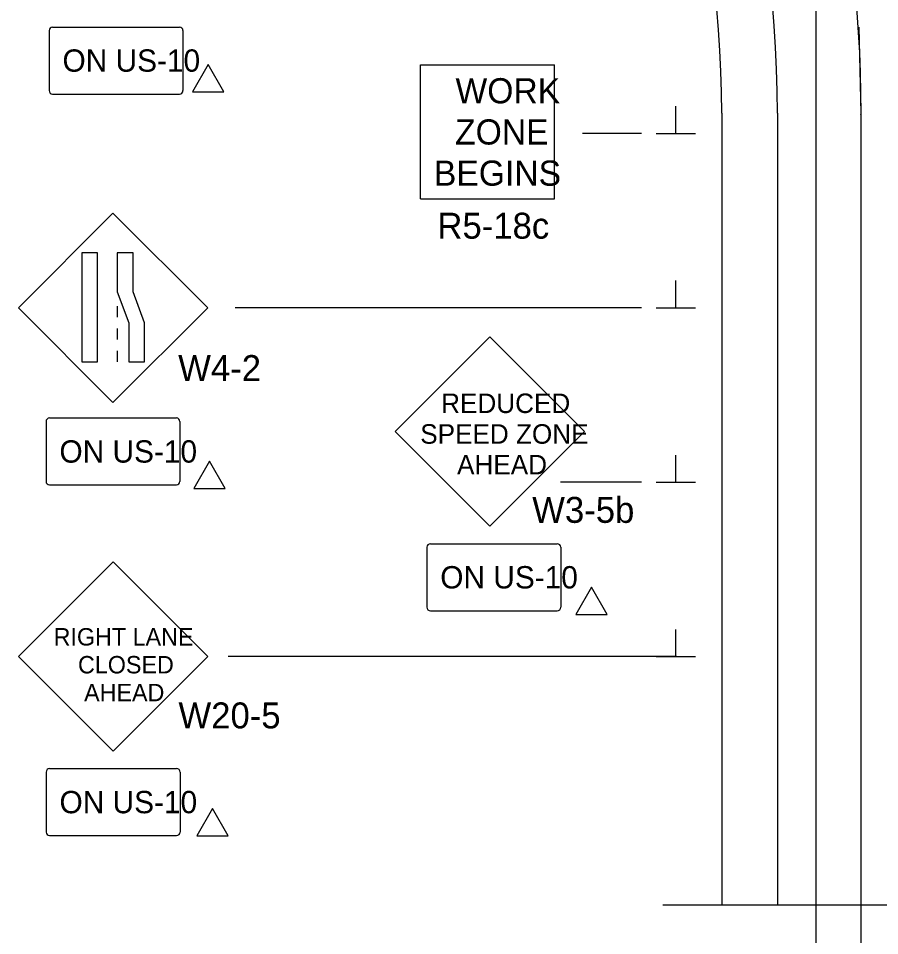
# Model space of a CAD drawing. Extents: x 16751 to 18479, y 5718 to 6974.
# Drawn here: x 16751.9 to 16999, y 6289.3 to 6552.3 of the extents above; entities that cross this region are included whole.
import ezdxf

# ---------------------------------------------------------------- set-up
doc = ezdxf.new("R2010")
doc.units = 0
for name, color, linetype in [('ALI_LEGAL_EX', 7, 'Continuous'), ('PAVT_EDGE_EX', 7, 'Continuous'), ('TRAFFIC_SIGNS_PR', 7, 'Continuous'), ('TYPICAL_TEXT_DIMEN_PR', 7, 'Continuous')]:
    doc.layers.add(name, color=color, linetype=linetype)

msp = doc.modelspace()

# ---------------------------------------------------------------- linework, layer by layer
at = {"layer": 'ALI_LEGAL_EX'}
for p, q in [((16980.68, 6974.12), (16980.68, 6155.98)), ((16980.68, 6877.04), (16980.68, 6013.12)), ((16993.65, 6024.8), (16993.65, 6525.15))]:
    msp.add_line(p, q, dxfattribs=at)
for points in [[(16993.6, 6524.8), (16993.65, 6525.15), (16993.08, 6549.79)], [(16993.65, 6424.8), (16993.65, 6449.8)], [(16993.7, 6349.8), (16993.7, 6374.8)]]:
    msp.add_lwpolyline(points, dxfattribs=at)
msp.add_arc((16629.65, 6525.15), 364, 0, 57.2958, dxfattribs=at)
at = {"layer": 'PAVT_EDGE_EX'}
for p, q in [((16953.65, 6525.15), (16953.65, 6298.02)), ((16969.65, 6525.15), (16969.65, 6298.02))]:
    msp.add_line(p, q, dxfattribs=at)
for radius in [340, 324]:
    msp.add_arc((16629.65, 6525.15), radius, 0, 66.0906, dxfattribs=at)
at = {"layer": 'TRAFFIC_SIGNS_PR'}
for p, q in [((16760.72, 6548.83), (16760.72, 6531.63)), ((16761.72, 6549.83), (16798.12, 6549.83)), ((16799.12, 6548.83), (16799.12, 6531.63)), ((16867.29, 6500.59), (16867.29, 6538.99)), ((16867.29, 6538.99), (16905.69, 6538.99)), ((16905.69, 6500.59), (16905.69, 6538.99)), ((16761.72, 6530.63), (16798.12, 6530.63)), ((16867.29, 6500.59), (16905.69, 6500.59)), ((16779.04, 6496.48), (16751.89, 6469.33)), ((16806.2, 6469.33), (16779.04, 6496.48)), ((16751.89, 6469.33), (16779.04, 6442.17)), ((16779.04, 6442.17), (16806.2, 6469.33)), ((16780.28, 6469.82), (16780.28, 6466.62)), ((16780.28, 6463.42), (16780.28, 6460.22)), ((16887.13, 6461), (16859.97, 6433.84)), ((16914.28, 6433.84), (16887.13, 6461)), ((16780.28, 6457.02), (16780.28, 6453.82)), ((16760.84, 6437.73), (16797.24, 6437.73)), ((16759.84, 6436.73), (16759.84, 6419.53)), ((16798.24, 6436.73), (16798.24, 6419.53)), ((16859.97, 6433.84), (16887.13, 6406.69)), ((16887.13, 6406.69), (16914.28, 6433.84)), ((16760.84, 6418.53), (16797.24, 6418.53)), ((16869.08, 6400.65), (16869.08, 6383.45)), ((16870.08, 6401.65), (16906.48, 6401.65)), ((16907.48, 6400.65), (16907.48, 6383.45)), ((16779.07, 6396.48), (16751.92, 6369.33)), ((16806.22, 6369.33), (16779.07, 6396.48)), ((16870.08, 6382.45), (16906.48, 6382.45)), ((16751.92, 6369.33), (16779.07, 6342.18)), ((16779.07, 6342.18), (16806.22, 6369.33)), ((16760.86, 6337.18), (16797.27, 6337.18)), ((16759.86, 6336.18), (16759.86, 6318.98)), ((16798.27, 6336.18), (16798.27, 6318.98)), ((16760.86, 6317.98), (16797.27, 6317.98))]:
    msp.add_line(p, q, dxfattribs=at)
for points in [[(16770.15, 6485.06), (16770.15, 6453.82), (16774.64, 6453.82), (16774.64, 6485.06)], [(16780.28, 6485.06), (16780.28, 6473.88), (16783.63, 6465), (16783.63, 6453.82), (16788.12, 6453.82), (16788.12, 6465), (16784.78, 6473.88), (16784.78, 6485.06)]]:
    msp.add_lwpolyline(points, close=True, dxfattribs=at)
for centre, start, end in [((16761.72, 6548.83), 90, 180), ((16798.12, 6548.83), 0, 90), ((16761.72, 6531.63), 180, 270), ((16798.12, 6531.63), 270, 0), ((16760.84, 6436.73), 90, 180), ((16797.24, 6436.73), 0, 90), ((16760.84, 6419.53), 180, 270), ((16797.24, 6419.53), 270, 0), ((16870.08, 6400.65), 90, 180), ((16906.48, 6400.65), 0, 90), ((16870.08, 6383.45), 180, 270), ((16906.48, 6383.45), 270, 0), ((16760.86, 6336.18), 90, 180), ((16797.27, 6336.18), 0, 90), ((16760.86, 6318.98), 180, 270), ((16797.27, 6318.98), 270, 0)]:
    msp.add_arc(centre, 1, start, end, dxfattribs=at)
at = {"layer": 'TYPICAL_TEXT_DIMEN_PR'}
for p, q in [((16940.52, 6519.33), (16940.52, 6527.11)), ((16930.65, 6519.33), (16913.76, 6519.33)), ((16934.9, 6519.33), (16946.15, 6519.33)), ((16940.52, 6469.33), (16940.52, 6477.11)), ((16930.65, 6469.33), (16814.04, 6469.33)), ((16934.9, 6469.33), (16946.15, 6469.33)), ((16940.52, 6419.33), (16940.52, 6427.11)), ((16930.65, 6419.33), (16907.42, 6419.33)), ((16934.9, 6419.33), (16946.15, 6419.33)), ((16940.52, 6369.33), (16940.52, 6377.11)), ((16940.65, 6369.33), (16812.07, 6369.33)), ((16934.9, 6369.33), (16946.15, 6369.33)), ((17002.72, 6298.02), (16936.78, 6298.02))]:
    msp.add_line(p, q, dxfattribs=at)
for points in [[(16806.32, 6539.08), (16801.8, 6531.24), (16810.85, 6531.24)], [(16806.74, 6425.32), (16802.21, 6417.48), (16811.26, 6417.48)], [(16916.3, 6389.23), (16911.77, 6381.39), (16920.82, 6381.39)], [(16807.57, 6325.75), (16803.05, 6317.92), (16812.1, 6317.92)]]:
    msp.add_lwpolyline(points, close=True, dxfattribs=at)

# ---------------------------------------------------------------- texts
at = {"layer": 'TRAFFIC_SIGNS_PR'}
for s, height, p in [('ON US-10', 6.4, (16764.56, 6537.03)), ('WORK', 7.217, (16877.29, 6527.96)), ('ZONE', 7.217, (16877.17, 6516.15)), ('BEGINS', 7.217, (16871.1, 6504.34)), ('R5-18c', 7.44, (16872.1, 6489.15)), ('W4-2', 7.441, (16797.74, 6448.32)), ('REDUCED', 5.6, (16873.18, 6439.15)), ('SPEED ZONE', 5.6, (16867.18, 6430.35)), ('ON US-10', 6.401, (16763.68, 6424.93)), ('AHEAD', 5.6, (16877.74, 6421.55)), ('W3-5b', 7.44, (16899.29, 6407.66)), ('ON US-10', 6.4, (16872.92, 6388.85)), ('RIGHT LANE', 4.999, (16762.01, 6372.48)), ('CLOSED', 4.999, (16769, 6364.48)), ('AHEAD', 4.999, (16770.75, 6356.49)), ('W20-5', 7.439, (16797.82, 6348.72)), ('ON US-10', 6.401, (16763.7, 6324.38))]:
    msp.add_text(s, height=height, dxfattribs=at).set_placement(p)

doc.saveas('drawing.dxf')
